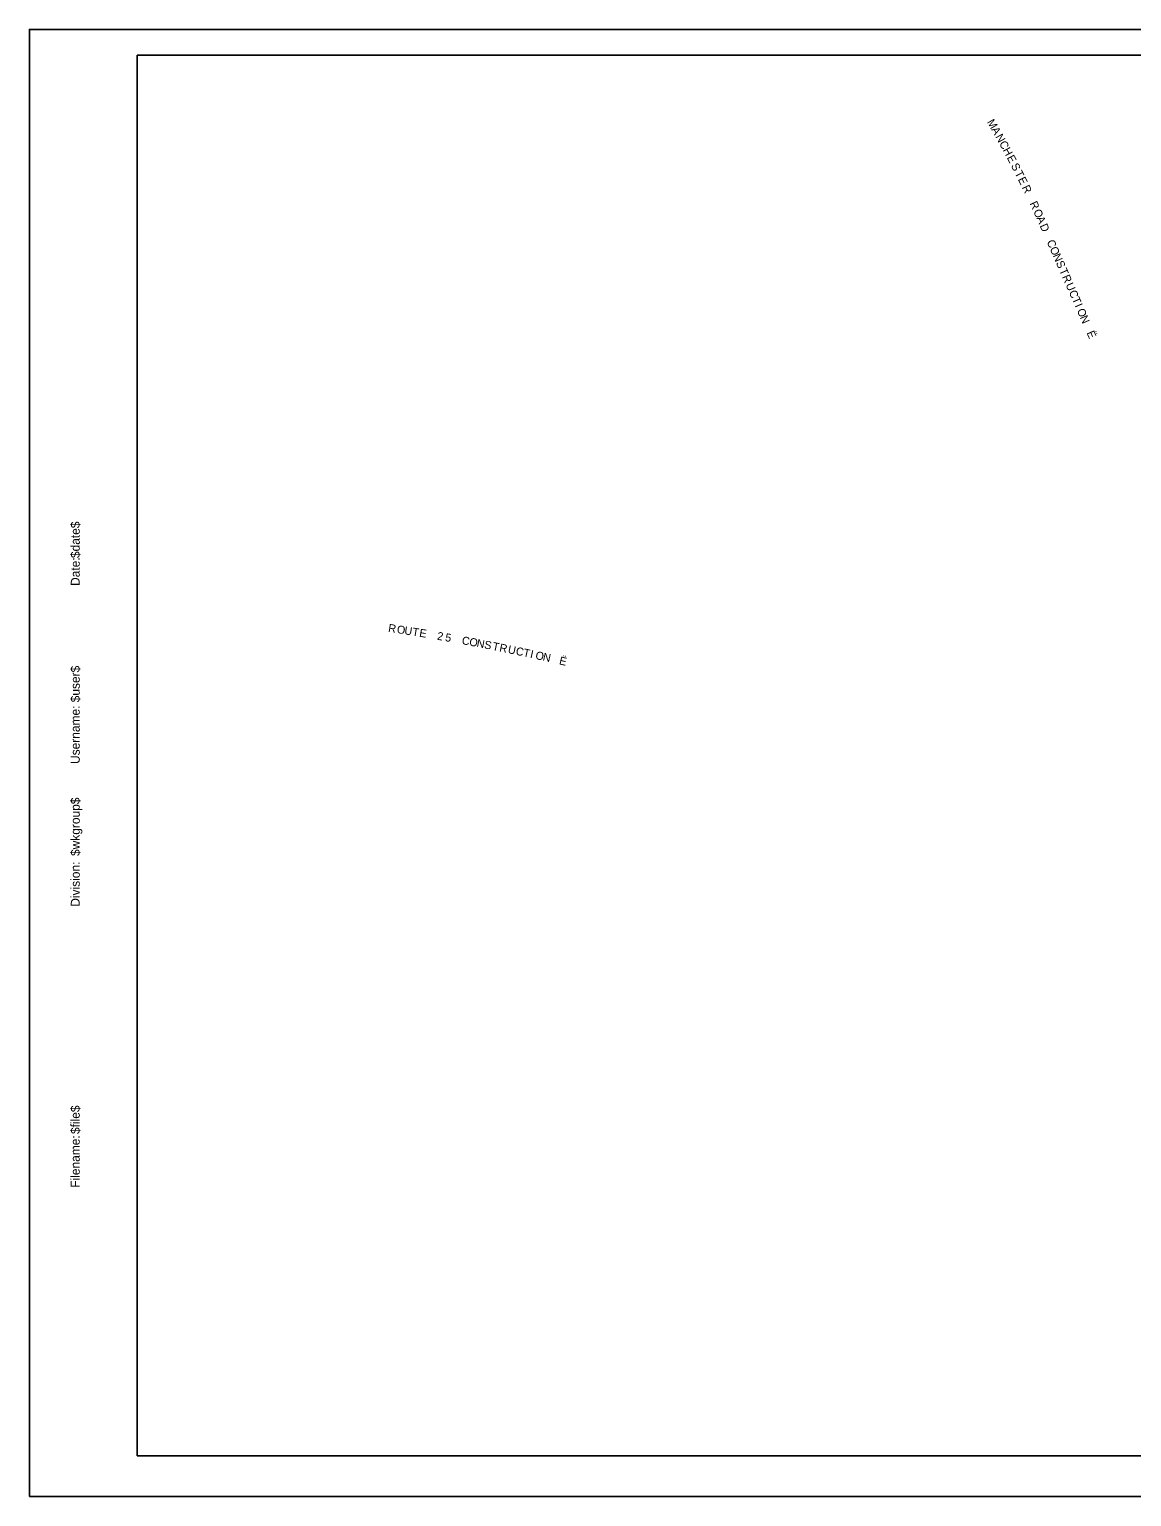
# Model space of a CAD drawing. Extents: x 916257 to 917115, y 329394 to 329944.
# Drawn here: x 916257 to 916670, y 329394 to 329944 of the extents above; entities that cross this region are included whole.
import ezdxf

# ---------------------------------------------------------------- set-up
doc = ezdxf.new("R2010")
doc.units = 0
for name, color, linetype in [('ANNOTATION', 7, 'Continuous'), ('Border', 7, 'Continuous'), ('PLOT BOUNDARY', 7, 'Continuous')]:
    doc.layers.add(name, color=color, linetype=linetype)

msp = doc.modelspace()

# ---------------------------------------------------------------- linework, layer by layer
at = {"layer": 'Border'}
for p, q in [((917097.47, 329934.21), (916297.47, 329934.21)), ((916297.47, 329934.21), (916297.47, 329409.21)), ((916297.47, 329409.21), (917097.47, 329409.21))]:
    msp.add_line(p, q, dxfattribs=at)
at = {"layer": 'PLOT BOUNDARY'}
msp.add_lwpolyline([(916257, 329393.91), (917107, 329393.91), (917107, 329943.91), (916257, 329943.91)], close=True, dxfattribs=at)

# ---------------------------------------------------------------- texts
at = {"layer": 'ANNOTATION'}
for s, rotation, p in [('M', 300.0194, (916615.88, 329909.18)), ('A', 299.531, (916617.51, 329906.36)), ('N', 299.069, (916619.03, 329903.68)), ('C', 298.635, (916620.44, 329901.15)), ('H', 298.2095, (916621.8, 329898.67)), ('E', 297.7261, (916623.32, 329895.83)), ('S', 297.2202, (916624.89, 329892.84)), ('T', 296.7547, (916626.31, 329890.08)), ('E', 296.3543, (916627.51, 329887.7)), ('R', 295.8485, (916629.01, 329884.68)), ('R', 294.8487, (916631.89, 329878.66)), ('O', 294.3589, (916633.26, 329875.7)), ('A', 293.9334, (916634.43, 329873.12)), ('D', 293.6677, (916635.68, 329870.3)), ('C', 293.6677, (916638.31, 329864.29)), ('O', 293.6677, (916639.45, 329861.7)), ('N', 293.6677, (916640.59, 329859.1)), ('S', 293.6677, (916641.75, 329856.45)), ('T', 293.6677, (916643, 329853.6)), ('R', 293.6677, (916644.07, 329851.16)), ('U', 293.6677, (916645.38, 329848.17)), ('C', 293.6677, (916646.59, 329845.42)), ('T', 293.6677, (916647.72, 329842.83)), ('I', 293.6677, (916648.8, 329840.38)), ('O', 293.6677, (916649.61, 329838.53)), ('N', 293.6677, (916650.74, 329835.93)), ('Ë', 293.6677, (916653.27, 329830.17)), ('R', 351.3612, (916391.39, 329718.12)), ('O', 351.1376, (916394.62, 329717.63)), ('U', 350.9434, (916397.42, 329717.19)), ('T', 350.7383, (916400.38, 329716.72)), ('E', 350.5555, (916403.02, 329716.29)), ('2', 350.0919, (916409.69, 329715.16)), ('5', 349.8831, (916412.7, 329714.64)), ('C', 349.4488, (916418.94, 329713.51)), ('O', 349.2546, (916421.73, 329712.99)), ('N', 349.0604, (916424.52, 329712.47)), ('S', 348.8623, (916427.36, 329711.92)), ('T', 348.6499, (916430.41, 329711.32)), ('R', 348.4671, (916433.02, 329710.79)), ('U', 348.2436, (916436.22, 329710.14)), ('C', 348.0384, (916439.16, 329709.53)), ('T', 347.8442, (916441.93, 329708.94)), ('I', 347.6615, (916444.54, 329708.38)), ('O', 347.5234, (916446.51, 329707.95)), ('N', 347.3292, (916449.28, 329707.34)), ('Ë', 346.8984, (916455.42, 329705.95))]:
    msp.add_text(s, height=3, rotation=rotation, dxfattribs=at).set_placement(p)
at = {"layer": 'Border'}
for s, p in [('$date$', (916275.89, 329745.73)), ('Date:', (916275.89, 329735.29)), ('$user$', (916275.89, 329691.67)), ('Username:', (916275.89, 329668.55)), ('$wkgroup$', (916275.89, 329634.06)), ('Division:', (916275.89, 329615.04)), ('$file$', (916275.89, 329529.84)), ('Filename:', (916275.89, 329509.7))]:
    msp.add_text(s, height=3.348, rotation=90, dxfattribs=at).set_placement(p)

doc.saveas('drawing.dxf')
